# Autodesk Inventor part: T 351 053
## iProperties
Company: Mayer & Müller AG Schaltgeräte
Created: 2006-10
Part Number: T 351 053
Material: AgNi 90/10
Document SubType Name: Modeling
Designer: I.Baliuc
Manufacturer: Standard
Standards Organization: Custom
Description: Silberplatte
Density: 10.49 g/cm^3
Author: T.Messerschmitt
Revision Number: 351053
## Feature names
1. Extrusion2
